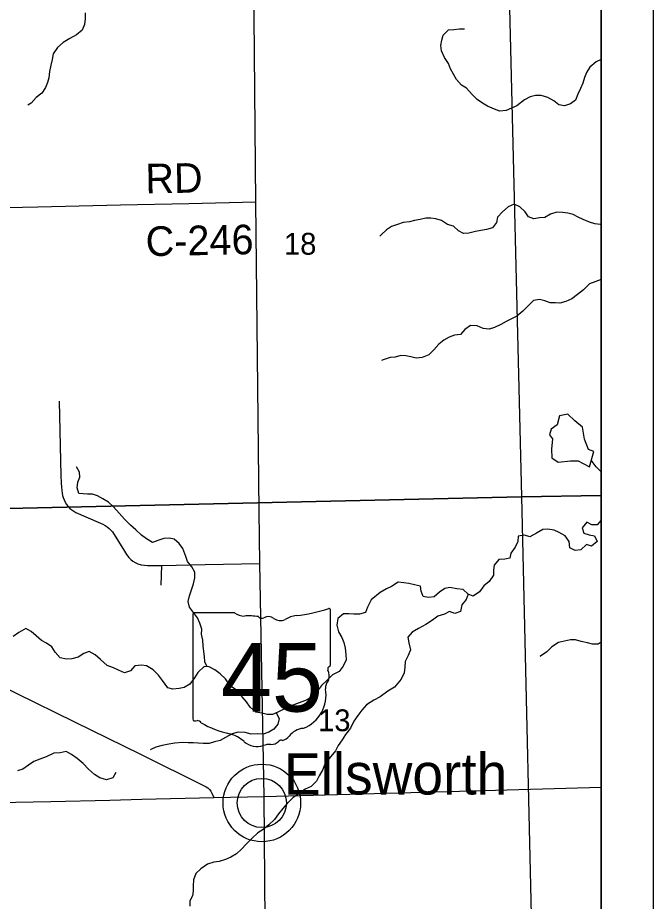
# Model space of a CAD drawing. Extents: x 0 to 34, y 0 to 22.
# Drawn here: x 9.124 to 10.344, y 16.025 to 17.72 of the extents above; entities that cross this region are included whole.
import ezdxf

# ---------------------------------------------------------------- set-up
doc = ezdxf.new("R2010")
doc.units = 0
for name, color, linetype in [('GM_X_Corporation', 7, 'Continuous'), ('GM_X_County_Road', 7, 'Continuous'), ('GM_X_County_Road_Text', 7, 'Continuous'), ('GM_X_Minor_Lake', 7, 'Continuous'), ('GM_X_Minor_River', 7, 'Continuous'), ('GM_X_Section_Text', 7, 'Continuous'), ('GM_X_State_Location', 7, 'Continuous'), ('GM_X_State_Route', 7, 'Continuous'), ('GM_X_State_Shield', 7, 'Continuous'), ('GM_X_Township_Road', 7, 'Continuous'), ('GM_X_Unincorporated', 7, 'Continuous'), ('GM_X_Unincorporated_Location', 7, 'Continuous'), ('GM_X_Unincorporated_Text', 7, 'Continuous'), ('GM_X_US_Route', 7, 'Continuous'), ('SH_Data', 7, 'Continuous')]:
    doc.layers.add(name, color=color, linetype=linetype)

msp = doc.modelspace()

# ---------------------------------------------------------------- linework, layer by layer
at = {"layer": 'GM_X_Corporation'}
msp.add_lwpolyline([(10.2438, 13.7323), (10.2438, 18.8341), (9.5705, 18.8263), (8.7622, 18.8099), (8.2239, 18.8028), (8.0146, 18.8), (7.0169, 18.7868), (7.0182, 18.7109), (7.0206, 18.595), (7.0233, 18.4737), (7.0259, 18.3381), (7.0286, 18.1986), (7.0307, 18.0432), (7.0341, 17.8886), (7.0383, 17.6784), (7.0382, 17.6446), (7.0667, 16.1653), (7.068, 16.109), (7.0714, 16.0063)], dxfattribs=at)
for points in [[(10.0662, 17.8169), (10.0909, 16.801), (9.0769, 16.778), (9.0559, 17.7965)], [(10.2438, 16.8039), (10.2438, 17.8207), (10.0662, 17.8169), (10.0909, 16.801)], [(10.0909, 16.801), (10.1146, 15.7786), (9.1033, 15.7563), (9.0769, 16.778)], [(10.2438, 15.7815), (10.2438, 16.8039), (10.0909, 16.801), (10.1146, 15.7786)]]:
    msp.add_lwpolyline(points, close=True, dxfattribs=at)
at = {"layer": 'GM_X_County_Road'}
for points in [[(9.581, 17.3663), (9.4524, 17.3631), (9.3215, 17.3603), (9.1629, 17.3567), (9.104, 17.355)], [(8.0538, 16.9541), (8.1531, 16.9041), (8.3861, 16.788), (8.6182, 16.6729), (8.7178, 16.6239), (8.9166, 16.5259), (9.1215, 16.4246), (9.233, 16.3699), (9.36, 16.3074), (9.4823, 16.2467)], [(9.4823, 16.2467), (9.4858, 16.2449), (9.4893, 16.2428), (9.4924, 16.2399), (9.4946, 16.2367), (9.4966, 16.2327), (9.5005, 16.2243)]]:
    msp.add_lwpolyline(points, dxfattribs=at)
at = {"layer": 'GM_X_Minor_Lake'}
for points in [[(10.2294, 16.8881), (10.2191, 16.8921), (10.2117, 16.9114), (10.2076, 16.9346), (10.1934, 16.9469), (10.1799, 16.9597), (10.164, 16.9564), (10.159, 16.9393), (10.1481, 16.9308), (10.1448, 16.9197), (10.1502, 16.9122), (10.1482, 16.8924), (10.1491, 16.8757), (10.161, 16.8675), (10.1849, 16.8704), (10.1993, 16.8702), (10.2092, 16.865), (10.2211, 16.8587)], [(10.2211, 16.8587), (10.2294, 16.8881)]]:
    msp.add_lwpolyline(points, dxfattribs=at)
at = {"layer": 'GM_X_Minor_River'}
for points in [[(9.2539, 17.7292), (9.254, 17.7178), (9.2523, 17.7071), (9.2482, 17.6961), (9.2373, 17.6872), (9.2241, 17.6798), (9.2113, 17.6721), (9.2008, 17.6628), (9.1926, 17.6506), (9.1901, 17.6395), (9.1876, 17.6288), (9.1855, 17.6166), (9.1837, 17.6048), (9.1812, 17.5953), (9.1779, 17.5858), (9.1704, 17.5754), (9.1595, 17.5666), (9.1502, 17.5562), (9.1434, 17.5523)], [(10.2438, 17.6399), (10.2344, 17.6351), (10.222, 17.6247), (10.2153, 17.6148), (10.212, 17.6052), (10.2087, 17.5942), (10.2043, 17.5842), (10.1987, 17.5735), (10.1947, 17.5617), (10.1849, 17.5548), (10.1732, 17.5508), (10.1625, 17.5526), (10.1526, 17.5604), (10.1411, 17.5668), (10.1289, 17.5704), (10.1179, 17.5707), (10.1077, 17.5679), (10.0964, 17.5624), (10.0817, 17.5508), (10.0719, 17.5462), (10.0617, 17.5422), (10.0496, 17.5409), (10.0393, 17.5442), (10.0259, 17.5502), (10.016, 17.5557), (10.0056, 17.5632), (9.996, 17.5726), (9.9852, 17.5846), (9.9757, 17.5906), (9.9661, 17.6015), (9.9602, 17.6117), (9.9548, 17.6215), (9.9505, 17.6321), (9.9431, 17.6434), (9.9373, 17.6562), (9.9364, 17.6665), (9.9381, 17.6767), (9.9407, 17.6863), (9.9508, 17.6963), (9.961, 17.6972), (9.972, 17.6988), (9.9815, 17.6986)], [(10.2438, 17.3236), (10.2421, 17.3233), (10.2315, 17.3243), (10.2212, 17.328), (10.2094, 17.3332), (10.1998, 17.3372), (10.1903, 17.3424), (10.1796, 17.3449), (10.1697, 17.346), (10.1587, 17.347), (10.1462, 17.343), (10.1357, 17.3368), (10.1251, 17.3359), (10.1148, 17.3339), (10.1045, 17.338), (10.0976, 17.3477), (10.0876, 17.3575), (10.0765, 17.3623), (10.0652, 17.3569), (10.0547, 17.3476), (10.0446, 17.3372), (10.0428, 17.3269), (10.0354, 17.3166), (10.0236, 17.3138), (10.013, 17.3121), (10.0028, 17.3097), (9.9899, 17.3069), (9.9797, 17.306), (9.9698, 17.3112), (9.9602, 17.3202), (9.9487, 17.3235), (9.9372, 17.331), (9.9266, 17.3343), (9.9167, 17.3357), (9.9072, 17.3352), (9.8962, 17.3328), (9.8856, 17.3307), (9.8758, 17.3283), (9.864, 17.327), (9.8527, 17.3235), (9.8417, 17.3192), (9.832, 17.313), (9.8218, 17.3037), (9.8188, 17.3007)], [(10.2438, 17.2177), (10.2333, 17.2141), (10.2212, 17.2094), (10.2099, 17.1979), (10.1983, 17.1894), (10.1874, 17.1809), (10.1757, 17.1754), (10.1647, 17.1723), (10.1552, 17.1729), (10.1457, 17.1728), (10.1358, 17.1772), (10.1252, 17.1794), (10.1138, 17.1773), (10.1044, 17.1677), (10.0932, 17.1573), (10.0819, 17.1477), (10.0717, 17.1423), (10.0615, 17.1376), (10.051, 17.1317), (10.0389, 17.1259), (10.0287, 17.1224), (10.0173, 17.1237), (10.0059, 17.1289), (9.9929, 17.1295)], [(9.9929, 17.1295), (9.9824, 17.1218), (9.9738, 17.1122), (9.9624, 17.1109), (9.9519, 17.1074), (9.9421, 17.1015), (9.9323, 17.0938), (9.9226, 17.0831), (9.9128, 17.0734), (9.9, 17.0683), (9.889, 17.0671), (9.8787, 17.0696), (9.8692, 17.0714), (9.8593, 17.072), (9.8487, 17.0689), (9.8392, 17.0684), (9.8275, 17.0644), (9.8222, 17.0628)], [(10.2438, 16.8489), (10.234, 16.8585), (10.2263, 16.8687), (10.2244, 16.8704)], [(9.4876, 16.4753), (9.483, 16.485), (9.4829, 16.4949), (9.4816, 16.5043), (9.4804, 16.5153), (9.4795, 16.5263), (9.477, 16.5377), (9.4773, 16.5476), (9.4737, 16.5586), (9.4691, 16.5692), (9.4536, 16.5895), (9.4516, 16.6005), (9.4537, 16.6115), (9.4574, 16.6226), (9.4614, 16.6344), (9.4639, 16.6455), (9.4642, 16.6565), (9.4583, 16.6667), (9.4502, 16.6772), (9.4467, 16.687), (9.4408, 16.7018), (9.4342, 16.7116), (9.4242, 16.7202), (9.4147, 16.722), (9.4049, 16.7211), (9.3928, 16.7175), (9.3826, 16.7136), (9.3715, 16.7203), (9.3615, 16.7278), (9.3508, 16.7376), (9.3404, 16.7465), (9.3293, 16.7582), (9.3192, 16.7695), (9.3081, 16.7819), (9.2985, 16.7909), (9.2878, 16.7972), (9.2771, 16.8028), (9.2675, 16.8061), (9.258, 16.806), (9.2417, 16.8077), (9.2382, 16.8183), (9.2399, 16.8293), (9.2432, 16.8388), (9.2427, 16.8483), (9.2373, 16.8585)], [(10.2438, 16.7562), (10.2358, 16.7472), (10.2255, 16.7475), (10.216, 16.7527), (10.207, 16.7415), (10.2102, 16.7317), (10.2205, 16.728), (10.2307, 16.7262), (10.2362, 16.7153), (10.2253, 16.7064), (10.2154, 16.7097), (10.2045, 16.6993), (10.1939, 16.6984), (10.1836, 16.7032), (10.1823, 16.7154), (10.1749, 16.7263), (10.1631, 16.733), (10.1535, 16.7375), (10.1414, 16.7388), (10.1319, 16.7383), (10.1198, 16.7313), (10.107, 16.7247), (10.0967, 16.7273), (10.0846, 16.726), (10.0836, 16.7153), (10.0784, 16.7046), (10.0706, 16.6931), (10.0685, 16.6832), (10.0586, 16.6816), (10.0476, 16.6807), (10.0383, 16.6703), (10.0369, 16.6608), (10.037, 16.6509), (10.0288, 16.639), (10.0186, 16.6306), (10.0101, 16.6191), (9.998, 16.6109), (9.9885, 16.6146), (9.9789, 16.6232), (9.9671, 16.625), (9.9534, 16.6271), (9.9436, 16.6255), (9.9334, 16.6181), (9.9236, 16.6093), (9.9127, 16.608), (9.9024, 16.6098), (9.8985, 16.62), (9.8968, 16.6295), (9.8858, 16.6324), (9.8747, 16.6349), (9.8648, 16.6363), (9.8542, 16.6373), (9.8414, 16.6292), (9.8316, 16.6249), (9.8199, 16.6179), (9.8026, 16.6036), (9.7952, 16.5895), (9.7916, 16.5795), (9.7802, 16.576), (9.7692, 16.5762), (9.7597, 16.5765), (9.7491, 16.5767), (9.7382, 16.5679), (9.7364, 16.5549), (9.74, 16.5424), (9.7462, 16.5315), (9.7498, 16.5217), (9.7526, 16.5111), (9.7539, 16.4989), (9.7547, 16.4887), (9.7488, 16.4764), (9.741, 16.4661)], [(9.9886, 16.6146), (9.9848, 16.6043), (9.9766, 16.594), (9.9737, 16.5814), (9.9631, 16.5775), (9.9528, 16.5811), (9.943, 16.5761), (9.9302, 16.5721), (9.92, 16.5644), (9.9072, 16.5563), (9.8933, 16.5489), (9.8809, 16.5415), (9.873, 16.5319), (9.8747, 16.5209), (9.8782, 16.508), (9.8731, 16.4969), (9.8679, 16.4851), (9.8673, 16.4748), (9.8659, 16.4634), (9.86, 16.4516), (9.8469, 16.4362), (9.8345, 16.4285), (9.8198, 16.4176), (9.8077, 16.411), (9.7934, 16.4025), (9.7844, 16.3921), (9.7766, 16.3818), (9.7692, 16.3707), (9.7629, 16.3577), (9.7532, 16.3454), (9.7465, 16.3351), (9.7394, 16.324), (9.7338, 16.314), (9.7252, 16.3033), (9.7144, 16.2906), (9.7096, 16.2784), (9.7025, 16.2661), (9.6974, 16.2558), (9.6872, 16.2458), (9.6759, 16.2404), (9.6631, 16.2307), (9.6526, 16.2245), (9.6413, 16.2133), (9.6331, 16.2037), (9.6245, 16.1934), (9.6167, 16.1823), (9.6058, 16.1719), (9.5949, 16.1634), (9.5851, 16.1568), (9.5739, 16.1464), (9.5626, 16.1349), (9.5536, 16.1253), (9.5439, 16.1164), (9.533, 16.1102), (9.5231, 16.1055), (9.5107, 16.1019), (9.5004, 16.1007), (9.4887, 16.0967), (9.4759, 16.0878), (9.4662, 16.0786), (9.4614, 16.0664), (9.4612, 16.055), (9.4609, 16.0455), (9.4595, 16.036), (9.4547, 16.0264), (9.4544, 16.0161)], [(9.741, 16.4661), (9.7282, 16.4598), (9.7173, 16.4491), (9.7072, 16.4391), (9.6997, 16.4291), (9.6896, 16.418), (9.6798, 16.4121), (9.6692, 16.4078), (9.659, 16.4043), (9.6469, 16.4), (9.6349, 16.3941), (9.6232, 16.3883), (9.6134, 16.384), (9.6031, 16.3839), (9.5928, 16.386), (9.581, 16.3885), (9.5703, 16.3979), (9.5633, 16.4077), (9.5549, 16.4175), (9.5422, 16.4314), (9.5322, 16.4385), (9.5229, 16.4524), (9.5129, 16.4614), (9.5022, 16.4696), (9.4919, 16.4752), (9.482, 16.4755), (9.47, 16.4643), (9.4637, 16.454), (9.4547, 16.4417), (9.4438, 16.4355), (9.434, 16.4338), (9.4222, 16.4322), (9.4123, 16.4347), (9.4023, 16.449), (9.3942, 16.4592), (9.3842, 16.4693), (9.3712, 16.4768), (9.3617, 16.4786), (9.3491, 16.4769), (9.3409, 16.4673), (9.3292, 16.4637), (9.3177, 16.4685), (9.3082, 16.4733), (9.2956, 16.4774), (9.2829, 16.489), (9.273, 16.4984), (9.2611, 16.5043), (9.2513, 16.5004), (9.2404, 16.4934), (9.2283, 16.4902), (9.2177, 16.4901), (9.2059, 16.4922), (9.1962, 16.5035), (9.19, 16.5137), (9.1797, 16.5204), (9.1698, 16.5256), (9.1594, 16.5346), (9.1498, 16.5428), (9.1399, 16.5488), (9.1263, 16.541), (9.1158, 16.5333)], [(10.2438, 16.5227), (10.2379, 16.5189), (10.2273, 16.5187), (10.2174, 16.5213), (10.2052, 16.5238), (10.1946, 16.5267), (10.1847, 16.5266), (10.162, 16.5217), (10.1488, 16.5136), (10.1394, 16.504), (10.1274, 16.4959), (10.1259, 16.4951)], [(9.6204, 16.3871), (9.626, 16.3758), (9.6235, 16.3655), (9.616, 16.3559), (9.6062, 16.3501), (9.5949, 16.3461), (9.5842, 16.3464), (9.5721, 16.3459), (9.5607, 16.3491), (9.5474, 16.3501), (9.536, 16.3466), (9.5228, 16.3396), (9.5127, 16.3337), (9.5021, 16.3313), (9.4919, 16.3278), (9.4801, 16.328), (9.4706, 16.3287), (9.4607, 16.3297), (9.4512, 16.3296), (9.4402, 16.3298), (9.4258, 16.3289), (9.4141, 16.3268), (9.4016, 16.3244), (9.3895, 16.3208), (9.3796, 16.3165), (9.3793, 16.3162)], [(9.3126, 16.2724), (9.3067, 16.2625), (9.2946, 16.2585), (9.282, 16.2625), (9.2717, 16.2685), (9.2598, 16.279), (9.2498, 16.2899), (9.2383, 16.2996), (9.2272, 16.3071), (9.2172, 16.3127), (9.2059, 16.3102), (9.1938, 16.3097), (9.1787, 16.3027), (9.1666, 16.298), (9.1549, 16.2937), (9.1447, 16.2867), (9.1338, 16.279), (9.124, 16.2754)]]:
    msp.add_lwpolyline(points, dxfattribs=at)
at = {"layer": 'GM_X_State_Route'}
msp.add_line((9.6021, 15.6624), (9.5969, 16.2262), dxfattribs=at)
for points in [[(9.5875, 16.7735), (9.581, 17.3663), (9.5729, 18.2936), (9.5715, 18.5043), (9.5707, 18.8257), (9.5594, 19.3287)], [(9.5969, 16.2262), (9.5886, 16.673), (9.5875, 16.7735)]]:
    msp.add_lwpolyline(points, dxfattribs=at)
at = {"layer": 'GM_X_State_Shield'}
for p, q in [((9.4605, 16.5753), (9.4605, 16.3752)), ((9.5404, 16.5787), (9.4631, 16.5787)), ((9.7242, 16.479), (9.7242, 16.5837)), ((9.7242, 16.479), (9.7242, 16.479))]:
    msp.add_line(p, q, dxfattribs=at)
for centre, radius, start, end in [((9.4636, 16.5757), 0.00305, 98.1301, 188.1301), ((9.5588, 16.602), 0.0296, 231.6195, 271.1119), ((9.5686, 16.4664), 0.1064, 80.4867, 94.9883), ((9.6053, 16.5536), 0.0178, 54.4667, 119.1411), ((9.666, 16.5176), 0.0563, 97.3462, 120.7689), ((9.6303, 16.8516), 0.2796, 275.8445, 288.9065), ((9.7213, 16.5841), 0.00294, 351.8621, 97.738), ((9.5927, 16.5767), 0.00855, 219.7921, 297.1024), ((9.6282, 16.5853), 0.0214, 233.8562, 294.8282), ((9.7235, 16.4713), 0.00454, 107.944, 210.337), ((9.7211, 16.4786), 0.00314, 289.6038, 7.7341), ((9.6946, 16.4581), 0.0273, 340.033, 23.6496), ((9.7347, 16.4352), 0.0198, 136.8065, 186.9296), ((9.646, 16.4219), 0.0699, 292.3089, 8.9858), ((9.4636, 16.3747), 0.00308, 171.9584, 258.3066), ((9.4641, 16.3952), 0.0235, 267.339, 280.6039), ((9.4689, 16.3636), 0.00848, 29.7484, 93.2717), ((9.5759, 16.5434), 0.2019, 240.4129, 257.1985), ((9.6754, 16.319), 0.0383, 94.4031, 142.5768), ((9.5157, 16.2853), 0.0632, 47.1842, 75.836), ((9.6295, 16.3283), 0.00601, 65.7517, 132.6484), ((9.6269, 16.3558), 0.0226, 282.8732, 323.2771), ((9.5841, 16.3626), 0.0401, 230.7004, 286.2918), ((9.6072, 16.2934), 0.0329, 85.6951, 111.2099), ((9.6102, 16.3476), 0.0214, 268.777, 315.5493)]:
    msp.add_arc(centre, radius, start, end, dxfattribs=at)
at = {"layer": 'GM_X_Township_Road'}
msp.add_line((9.3992, 16.632), (9.4006, 16.6695), dxfattribs=at)
msp.add_lwpolyline([(9.2039, 16.9845), (9.2072, 16.8423), (9.2077, 16.8281), (9.2083, 16.8198), (9.2088, 16.8134), (9.2094, 16.808), (9.2103, 16.8036), (9.2117, 16.7996), (9.2133, 16.7952), (9.2152, 16.7906), (9.2179, 16.7864), (9.2211, 16.7827), (9.2245, 16.7789), (9.2298, 16.7748), (9.2355, 16.7713), (9.2789, 16.7524), (9.2874, 16.7486), (9.292, 16.7461), (9.296, 16.7435), (9.2995, 16.7407), (9.303, 16.7374), (9.3059, 16.7343), (9.3291, 16.6967), (9.3332, 16.6905), (9.3373, 16.685), (9.3411, 16.6809), (9.345, 16.678), (9.3498, 16.675), (9.3547, 16.6729), (9.3613, 16.671), (9.3674, 16.67), (9.3736, 16.6697), (9.3806, 16.6695), (9.3871, 16.6694), (9.3931, 16.6694), (9.4006, 16.6695), (9.4842, 16.6711), (9.5886, 16.673)], dxfattribs=at)
at = {"layer": 'GM_X_Unincorporated'}
for radius in [0.0744, 0.0472]:
    msp.add_circle((9.5927, 16.2141), radius, dxfattribs=at)
at = {"layer": 'GM_X_Unincorporated_Location'}
msp.add_line((9.5927, 16.2141), (9.5927, 16.2141), dxfattribs=at)
at = {"layer": 'GM_X_US_Route'}
for p, q in [((9.5969, 16.2262), (9.9954, 16.2374)), ((9.9954, 16.2374), (10.2438, 16.2444))]:
    msp.add_line(p, q, dxfattribs=at)
for points in [[(7.0669, 16.1647), (7.0746, 16.1643), (7.0844, 16.1637), (7.0963, 16.1634), (7.1618, 16.1645), (7.825, 16.1797), (7.8946, 16.1823), (7.9604, 16.1847), (8.0272, 16.1873), (8.0709, 16.1891), (8.167, 16.1931), (8.3066, 16.1984), (8.3428, 16.1995), (8.4171, 16.2016), (8.4871, 16.2031), (8.5373, 16.2045), (8.674, 16.2072), (8.8546, 16.2105), (9.0191, 16.2135), (9.188, 16.2172), (9.3008, 16.2197)], [(9.3008, 16.2197), (9.3627, 16.2211), (9.5005, 16.2243), (9.5969, 16.2262)]]:
    msp.add_lwpolyline(points, dxfattribs=at)
at = {"layer": 'SH_Data'}
for p, q in [((10.3438, 20.0239), (10.3438, 13.0239)), ((10.2438, 19.9239), (10.2438, 13.1239))]:
    msp.add_line(p, q, dxfattribs=at)

# ---------------------------------------------------------------- texts
at = {"layer": 'GM_X_County_Road_Text'}
for s, rotation, p in [('RD', 0.9872, (9.3697, 17.3828)), ('C-246', 1.1011, (9.3703, 17.2625))]:
    msp.add_text(s, height=0.05682, rotation=rotation, dxfattribs=at).set_placement(p)
at = {"layer": 'GM_X_Section_Text'}
for s, p in [('18', (9.6351, 17.2654)), ('13', (9.7005, 16.3517))]:
    msp.add_text(s, height=0.04186, rotation=0, dxfattribs=at).set_placement(p)
at = {"layer": 'GM_X_State_Location'}
for s in ['s', 'r']:
    msp.add_text(s, height=0.000189, dxfattribs=at).set_placement((9.5894, 16.4619))
msp.add_text('45', height=0.000189, rotation=0, dxfattribs=at).set_placement((9.5417, 16.4481))
at = {"layer": 'GM_X_State_Shield'}
msp.add_text('45', height=0.13184, dxfattribs=at).set_placement((9.5139, 16.3893))
at = {"layer": 'GM_X_Unincorporated_Text'}
msp.add_text('Ellsworth', height=0.07898, rotation=0, dxfattribs=at).set_placement((9.6351, 16.2303))

doc.saveas('drawing.dxf')
